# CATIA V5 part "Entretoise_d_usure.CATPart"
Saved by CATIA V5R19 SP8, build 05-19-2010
Part number: Entretoise_d_usure
Bounding box of the stored display mesh (mm): x -22.5 to 22.5, y -22.5 to 22.5, z 1100 to 1223
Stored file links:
  G:\EU_thinkMotion\CFAO_2010\MMS_groupe2\MMS_groupe2\OK\nrosalie\nrosalie_cfao_support_d_arme_legere_final\Entretoise_d_usure.CATPart
  G:\EU_thinkMotion\CFAO_2010\MMS_groupe2\MMS_groupe2\OK\nrosalie\nrosalie_cfao_support_d_arme_legere_final\nrosalie_Support_d_arme_legere.CATProduct
  G:\EU_thinkMotion\CFAO_2010\MMS_groupe2\MMS_groupe2\OK\nrosalie\nrosalie_cfao_support_d_arme_legere_final\Squelette_Colone.CATPart
  G:\EU_thinkMotion\CFAO_2010\MMS_groupe2\MMS_groupe2\OK\nrosalie\nrosalie_cfao_support_d_arme_legere_final\Axe_liaison_pivot.CATPart
  G:\EU_thinkMotion\CFAO_2010\MMS_groupe2\MMS_groupe2\OK\nrosalie\nrosalie_cfao_support_d_arme_legere_final\NAO_40x55x17_PART1.CATPart
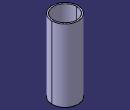
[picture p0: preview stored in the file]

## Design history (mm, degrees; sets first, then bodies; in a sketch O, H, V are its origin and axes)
Set1
  Sketch1 on Plane1, origin (0, 0, 1100), H (1, 0, 0), V (0, 1, 0)
    circle A1 centre (0, 0) radius 20
    reference projected circle E1 centre (0, 0) radius 20 from edge of DatumCurve1
    circle A2 centre (0, 0) radius 22.5
    distance A2 A1 = 2.5
    coincidence: A1 E1
    concentricity: A2 A1
Set2
  Plane1 "Plan_limite_inferieur_liaison_pivot_colone_systeme": linked copy from another document
  DatumCurve1: linked copy from another document
  DatumSurface1: linked copy from another document
Body1 (main body)
  Pad1: profile Sketch1, direction (0, 0, 1), up to face of DatumSurface1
